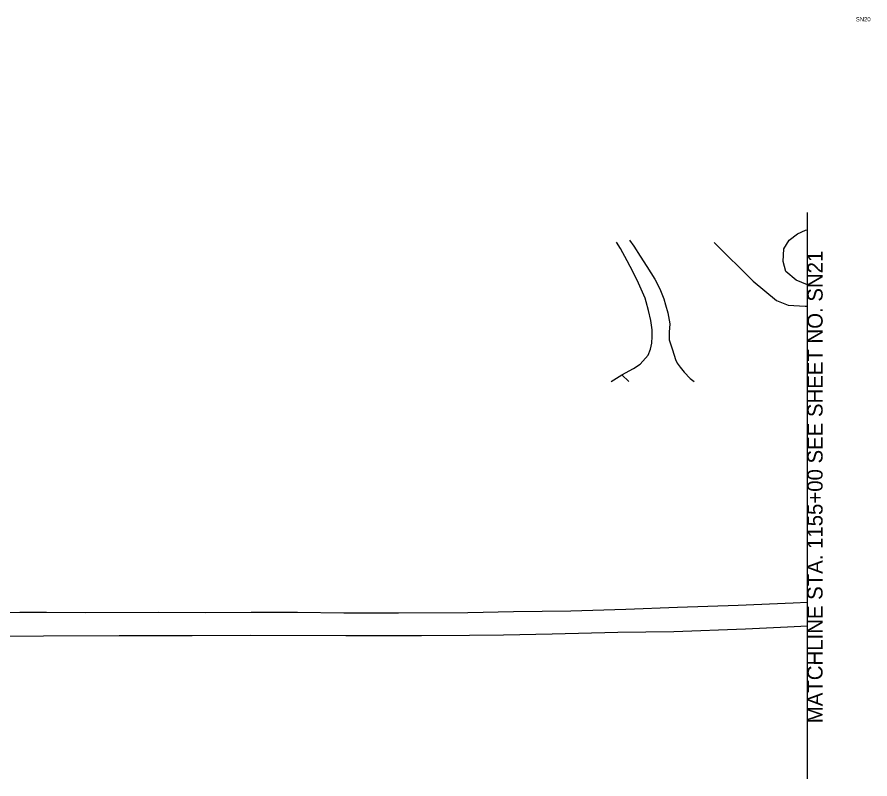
# Model space of a CAD drawing. Extents: x 1738684 to 1740272, y 1164618 to 1165340.
# Drawn here: x 1739478 to 1740272, y 1164631 to 1165340 of the extents above; entities that cross this region are included whole.
import ezdxf

# ---------------------------------------------------------------- set-up
doc = ezdxf.new("R2010")
doc.units = 0
for name, color, linetype in [('RD_EX_Conc', 7, 'Continuous'), ('RD_EX_Driveway', 7, 'Continuous'), ('RD_EX_Road', 7, 'Continuous'), ('RD_SHT_MatchLine', 7, 'Continuous'), ('RD_SHT_TX', 7, 'Continuous')]:
    doc.layers.add(name, color=color, linetype=linetype)

msp = doc.modelspace()

# ---------------------------------------------------------------- linework, layer by layer
at = {"layer": 'RD_EX_Conc'}
msp.add_lwpolyline([(1740030.81, 1165000.79), (1740040.78, 1165007.22), (1740047.3, 1165000.79)], dxfattribs=at)
at = {"layer": 'RD_EX_Driveway'}
for points in [[(1740213.73, 1165090.99), (1740203.09, 1165095.09), (1740193.66, 1165103.16), (1740190.97, 1165112.7), (1740191.82, 1165124.32), (1740196.83, 1165132.39), (1740204.29, 1165138.27), (1740211.99, 1165141.58), (1740213.73, 1165142.08)], [(1740040.78, 1165007.22), (1740051.68, 1165012.84), (1740058.01, 1165017.11), (1740065.53, 1165025.32), (1740067.72, 1165030.85), (1740068.75, 1165036.63), (1740069.18, 1165042.72), (1740069.24, 1165049), (1740067.8, 1165057.61), (1740065.7, 1165067.08), (1740063.47, 1165075.15), (1740062.46, 1165078.39), (1740056.38, 1165092.29), (1740051.31, 1165102.71), (1740045.74, 1165113.12), (1740039.64, 1165124.58), (1740035.86, 1165130.47)], [(1740047.95, 1165132.42), (1740052.1, 1165126.83), (1740057.92, 1165117.51), (1740064.28, 1165107.87), (1740071.61, 1165096.21), (1740076.27, 1165086.96), (1740080.14, 1165077.65), (1740081.67, 1165072.33), (1740083.61, 1165064.81), (1740085.58, 1165054.66), (1740085.08, 1165046.74), (1740085, 1165039.6), (1740088.21, 1165030.42), (1740090.74, 1165021.42), (1740092.54, 1165017.8), (1740095.12, 1165014.05), (1740098.86, 1165009.5), (1740104.36, 1165003.64), (1740108.31, 1165000.79)], [(1740126.75, 1165130.34), (1740163.22, 1165094.15), (1740184.76, 1165076.19), (1740195.89, 1165071.79), (1740211.67, 1165070.83), (1740213.73, 1165070.9)]]:
    msp.add_lwpolyline(points, dxfattribs=at)
at = {"layer": 'RD_EX_Road'}
for points in [[(1739426.94, 1164786.02), (1739480.37, 1164786.05), (1739505.25, 1164786.18), (1739541.23, 1164785.97), (1739609.38, 1164786.27), (1739653.07, 1164785.92), (1739695.83, 1164786.18), (1739738.77, 1164786.14), (1739782.13, 1164785.55), (1739832.94, 1164785.71), (1739897.41, 1164785.85), (1739940.13, 1164786.7), (1739993.32, 1164787.5), (1740044.47, 1164788.82), (1740092.59, 1164790.74), (1740149.31, 1164792.82), (1740200.45, 1164794.83), (1740213.73, 1164795.43)], [(1739457.85, 1164763.83), (1739502.34, 1164764.18), (1739573.02, 1164764.38), (1739640.97, 1164764.5), (1739695.25, 1164764.64), (1739783.79, 1164764.39), (1739854.49, 1164764.41), (1739899.21, 1164764.87), (1739930.8, 1164765.16), (1739976.12, 1164766.05), (1740037.24, 1164767.5), (1740089.27, 1164768.08), (1740156.13, 1164770.78), (1740195.19, 1164772.66), (1740213.73, 1164773.58)]]:
    msp.add_lwpolyline(points, dxfattribs=at)
at = {"layer": 'RD_SHT_MatchLine'}
msp.add_lwpolyline([(1740213.74, 1164630.96), (1740213.73, 1164894.04), (1740213.73, 1165158.28)], dxfattribs=at)

# ---------------------------------------------------------------- texts
at = {"layer": 'RD_SHT_TX'}
msp.add_text('SN20', height=4, dxfattribs=at).set_placement((1740258.72, 1165336))
msp.add_text('MATCHLINE STA. 1155+00 SEE SHEET NO. SN21', height=14.1726, rotation=89.98556, dxfattribs=at).set_placement((1740227.77, 1164682.84))

doc.saveas('drawing.dxf')
